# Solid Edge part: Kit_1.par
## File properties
Sűrűség: 0,000 kg/m^3
Pontosság: 0,990
Author: bmolnar
Last saved by: bmolnar
Revision: 77
Username: bmolnar
Dokumentum tartalom típus: 0
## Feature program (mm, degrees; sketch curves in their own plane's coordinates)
base feature "unnamed BaseFeature 1"
sketch for "unnamed Cutout 1" plane through (-0.0012, 0, 85.35) normal (0, 0, -1) x-axis (-1, 0, 0)
  circle centre (-0.0012, 0) radius 8
extrude "unnamed Cutout 1" cut through along -normal
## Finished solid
Body 1: solid body, 46 faces, 63 edges, 49 vertices, 1 internal void.
  Faces by surface: cylinder 16, cone 14, plane 12, torus 4
  Edges by curve: circle 49, line 14
Bounding box of the edges (mm; curved faces can reach further): 68.000 x 67.800 x 14.500, from (-34, -32.35, 85.35) to (34, 35.45, 99.85).
Cylindrical faces by radius (mm): R1.5 x2, R3 x4, R8 x1, R8.27 x1, R8.85 x1, R9 x1, R10.16 x1, R10.25 x1, R19.25 x1, R29.65 x1, R32.35 x1, R34 x1
Conical faces (half-angle, radius in mm at the cone's reference point): 3 deg R10.205 x1, 7 deg R9.5925 x1, 14 deg R8.135 x1, 14 deg R8.4811 x1, 17 deg R8.135 x1, 23 deg R8.829 x1, 42.5 deg R8.1233 x1, 45 deg R9.1 x2, 45 deg R18.75 x1, 84 deg R76.3675 x2, 85 deg R9.9463 x1, 87 deg R8.1765 x1
Toroidal faces (ring radius, tube radius in mm): R8.8057 r0.2025 x1, R9.2522 r0.2925 x1, R9.96 r0.2 x1, R20.05 r0.8 x1
Planar faces by outward normal: +z 7, -z 3, oblique 2
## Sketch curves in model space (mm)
circle centre (0, 0, 85.35) radius 8
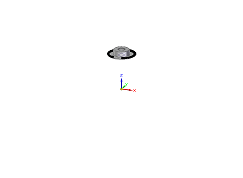
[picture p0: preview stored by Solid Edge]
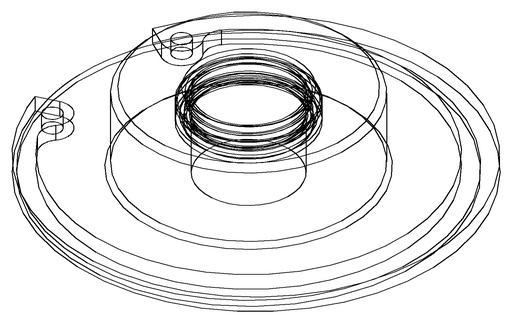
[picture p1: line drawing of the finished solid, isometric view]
